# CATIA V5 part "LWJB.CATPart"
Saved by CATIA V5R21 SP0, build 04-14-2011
Part number: LWJB.SLDPRT
Bounding box of the stored display mesh (mm): x -1.362 to 1.338, y -0.976 to 1.024, z 2.1 to 2.7
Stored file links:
  C:\Users\user\Desktop\CATIA文件\LWJB\LWJB.CATPart
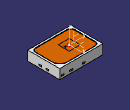
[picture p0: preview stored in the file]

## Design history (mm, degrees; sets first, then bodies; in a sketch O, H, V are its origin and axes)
AxisSystem1: origin (-0.2515, 0.0244, 2.69), X (0, 1, 0), Y (-1, 0, 0), Z (0, 0, 1)
Set1
  DatumSurface1 to DatumSurface42
  Line1: stored without definition
  Circle1: stored without definition
  Line2: stored without definition
  Circle2: stored without definition
  Line3: stored without definition
  Circle3: stored without definition
  Line4: stored without definition
  Circle4: stored without definition
  Line5: stored without definition
  Circle5: stored without definition
  Line6: stored without definition
  Circle6: stored without definition
  Line7: stored without definition
  Circle7: stored without definition
  Line8: stored without definition
  Line9: stored without definition
  Circle8: stored without definition
  Line10: stored without definition
  Line11: stored without definition
  Circle9: stored without definition
  Line12: stored without definition
  Line13: stored without definition
  Circle10: stored without definition
  Line14 to Line18: stored without definition
  Circle11: stored without definition
  Line19: stored without definition
  Circle12: stored without definition
  Line20: stored without definition
  Circle13: stored without definition
  Line21: stored without definition
  Circle14: stored without definition
  Line22: stored without definition
  Circle15: stored without definition
  Line23: stored without definition
  Circle16: stored without definition
  Line24: stored without definition
  Circle17: stored without definition
  Line25: stored without definition
  Circle18: stored without definition
  Line26: stored without definition
  Circle19: stored without definition
  Line27: stored without definition
  Circle20: stored without definition
  Line28 to Line30: stored without definition
  Circle21: stored without definition
  Line31: stored without definition
  Circle22: stored without definition
  Line32: stored without definition
  Circle23: stored without definition
  Line33: stored without definition
  Circle24: stored without definition
  Line34: stored without definition
  Line35: stored without definition
  Circle25: stored without definition
  Line36: stored without definition
  Circle26: stored without definition
  Line37: stored without definition
  Circle27: stored without definition
  Line38: stored without definition
  Circle28: stored without definition
  Line39: stored without definition
  Circle29: stored without definition
  Line40: stored without definition
  Circle30: stored without definition
  Line41: stored without definition
  Circle31: stored without definition
  Line42: stored without definition
  Circle32: stored without definition
  Line43: stored without definition
  Circle33: stored without definition
  Line44 to Line46: stored without definition
  Circle34: stored without definition
  Line47: stored without definition
  Circle35: stored without definition
  Line48: stored without definition
  Circle36: stored without definition
  Line49: stored without definition
  Circle37: stored without definition
  Line50: stored without definition
  Circle38: stored without definition
  Line51 to Line79: stored without definition
  DatumSurface43 to DatumSurface79
  Line80: stored without definition
  Circle39: stored without definition
  Line81: stored without definition
  Circle40: stored without definition
  Line82: stored without definition
  Circle41: stored without definition
  Line83: stored without definition
  Circle42: stored without definition
  Circle43: stored without definition
  Line84 to Line87: stored without definition
  Circle44: stored without definition
  Line88 to Line90: stored without definition
  Circle45: stored without definition
  Line91 to Line93: stored without definition
  Circle46: stored without definition
  Line94: stored without definition
  Line95: stored without definition
  Circle47: stored without definition
  Line96: stored without definition
  Circle48: stored without definition
  Line97: stored without definition
  Circle49: stored without definition
  Line98 to Line100: stored without definition
  Circle50: stored without definition
  Line101: stored without definition
  Circle51: stored without definition
  Line102: stored without definition
  Circle52: stored without definition
  Line103: stored without definition
  Circle53: stored without definition
  Line104: stored without definition
  Circle54: stored without definition
  Line105 to Line107: stored without definition
  Circle55: stored without definition
  Line108: stored without definition
  Circle56: stored without definition
  Line109 to Line112: stored without definition
  Circle57: stored without definition
  Line113: stored without definition
  Circle58: stored without definition
  Line114: stored without definition
  Circle59: stored without definition
  Line115 to Line117: stored without definition
  Circle60: stored without definition
  Line118: stored without definition
  Circle61: stored without definition
  Line119: stored without definition
  Circle62: stored without definition
  Line120: stored without definition
  Circle63: stored without definition
  Line121: stored without definition
  Circle64: stored without definition
  Line122 to Line124: stored without definition
  Circle65: stored without definition
  Line125: stored without definition
  Circle66: stored without definition
  Line126 to Line153: stored without definition
  DatumSurface80 to DatumSurface173
  Circle67: stored without definition
  Line154: stored without definition
  Circle68: stored without definition
  Line155: stored without definition
  Circle69: stored without definition
  DatumCurve1
  Circle70: stored without definition
  DatumCurve2
  Circle71: stored without definition
  Line156: stored without definition
  Line157: stored without definition
  Circle72: stored without definition
  Line158: stored without definition
  Line159: stored without definition
  Circle73: stored without definition
  DatumCurve3
  DatumCurve4
  Circle74: stored without definition
  DatumCurve5
  DatumCurve6
  Circle75: stored without definition
  Line160: stored without definition
  Line161: stored without definition
  Circle76: stored without definition
  Line162: stored without definition
  Line163: stored without definition
  Circle77: stored without definition
  DatumCurve7
  DatumCurve8
  Circle78: stored without definition
  DatumCurve9
  DatumCurve10
  Line164 to Line166: stored without definition
  Circle79: stored without definition
  Line167: stored without definition
  Circle80: stored without definition
  Line168 to Line170: stored without definition
  Circle81: stored without definition
  Line171: stored without definition
  Circle82: stored without definition
  Line172 to Line174: stored without definition
  Circle83: stored without definition
  Line175: stored without definition
  Circle84: stored without definition
  Line176 to Line178: stored without definition
  Circle85: stored without definition
  Line179: stored without definition
  Circle86: stored without definition
  Line180: stored without definition
  Line181: stored without definition
  Circle87: stored without definition
  Line182: stored without definition
  Circle88: stored without definition
  Line183: stored without definition
  Circle89: stored without definition
  Line184 to Line186: stored without definition
  Circle90: stored without definition
  Line187: stored without definition
  Circle91: stored without definition
  Line188: stored without definition
  Circle92: stored without definition
  Line189: stored without definition
  Circle93: stored without definition
  Line190: stored without definition
  Circle94: stored without definition
  Line191 to Line193: stored without definition
  Circle95: stored without definition
  Line194: stored without definition
  Circle96: stored without definition
  Line195 to Line197: stored without definition
  Circle97: stored without definition
  Line198: stored without definition
  Line199: stored without definition
  Circle98: stored without definition
  Line200: stored without definition
  Line201: stored without definition
  Circle99: stored without definition
  Line202 to Line208: stored without definition
  Circle100: stored without definition
  Line209 to Line212: stored without definition
  Circle101: stored without definition
  Line213 to Line215: stored without definition
  Circle102: stored without definition
  Line216 to Line219: stored without definition
  Circle103: stored without definition
  Line220 to Line222: stored without definition
  Circle104: stored without definition
  Line223 to Line228: stored without definition
  Circle105: stored without definition
  Line229 to Line231: stored without definition
  Circle106: stored without definition
  Line232 to Line237: stored without definition
  DatumCurve11
  Line238: stored without definition
  DatumCurve12
  Line239: stored without definition
  DatumCurve13
  Line240 to Line245: stored without definition
  Circle107: stored without definition
  Line246: stored without definition
  Circle108: stored without definition
  Line247: stored without definition
  Circle109: stored without definition
  Line248: stored without definition
  Circle110: stored without definition
  Line249: stored without definition
  Circle111: stored without definition
  Line250: stored without definition
  Circle112: stored without definition
  Line251: stored without definition
  Circle113: stored without definition
  Line252: stored without definition
  Circle114: stored without definition
  Line253 to Line261: stored without definition
  DatumCurve14
  Line262: stored without definition
  DatumCurve15
  Line263: stored without definition
  Circle115: stored without definition
  Line264: stored without definition
  Circle116: stored without definition
  Line265: stored without definition
  Circle117: stored without definition
  Line266: stored without definition
  Circle118: stored without definition
  Line267: stored without definition
  Circle119: stored without definition
  Line268: stored without definition
  Circle120: stored without definition
  Line269: stored without definition
  Circle121: stored without definition
  Line270: stored without definition
  Circle122: stored without definition
  Line271: stored without definition
  Circle123: stored without definition
  Line272: stored without definition
  Circle124: stored without definition
  Line273: stored without definition
  Circle125: stored without definition
  Line274 to Line276: stored without definition
  Circle126: stored without definition
  Line277: stored without definition
  Line278: stored without definition
  Circle127: stored without definition
  Line279: stored without definition
  Circle128: stored without definition
  Line280: stored without definition
  Circle129: stored without definition
  Line281: stored without definition
  Circle130: stored without definition
  Line282: stored without definition
  Circle131: stored without definition
  Line283: stored without definition
  Circle132: stored without definition
  Line284: stored without definition
  Circle133: stored without definition
  Line285: stored without definition
  Circle134: stored without definition
  Line286: stored without definition
  Circle135: stored without definition
  Line287: stored without definition
  Circle136: stored without definition
  Line288 to Line290: stored without definition
  Circle137: stored without definition
  Line291: stored without definition
  Circle138: stored without definition
  Line292: stored without definition
  Circle139: stored without definition
  Line293: stored without definition
  Circle140: stored without definition
  Line294 to Line318: stored without definition
  Circle141: stored without definition
  Line319: stored without definition
  Line320: stored without definition
  Circle142: stored without definition
  Line321 to Line323: stored without definition
  Circle143: stored without definition
  Line324 to Line350: stored without definition
  DatumSurface174 to DatumSurface177
  DatumCurve16 to DatumCurve43
  DatumSurface178 to DatumSurface186
  DatumCurve44 to DatumCurve63
  Line351 to Line364: stored without definition
  DatumSurface187
  DatumCurve64 to DatumCurve67
  Point1 "几何中心": type Between, FirstPoint vertex [face of DatumSurface171], SecondPoint vertex [face of DatumSurface168], Ratio 0.5
  Point2 "发光中心（测试原点）": type Between, FirstPoint vertex [face of DatumSurface187], SecondPoint vertex [face of DatumSurface187], Ratio 0.5
  Point3 "虚拟焦点": (0.0123, 0.0098, -0.0756), relative to Point2, in AxisSystem1
Body1 (main body)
